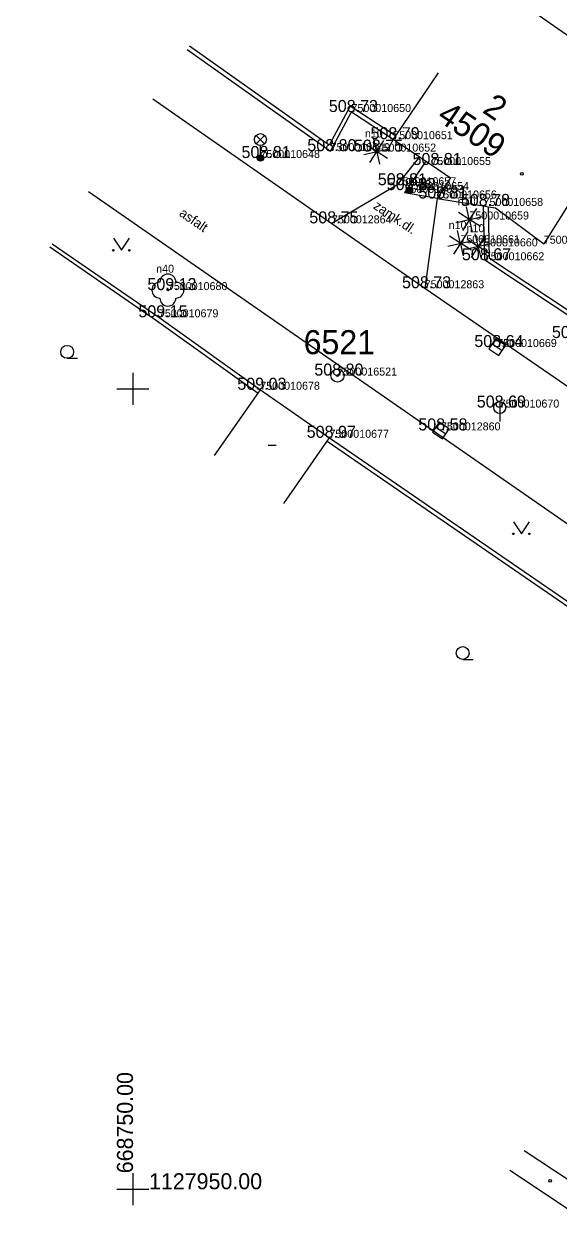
# Model space of a CAD drawing. Extents: x -669251 to -668549, y -1128351 to -1127698.
# Drawn here: x -668756.8 to -668723.4, y -1127952.2 to -1127877.2 of the extents above; entities that cross this region are included whole.
import ezdxf

# ---------------------------------------------------------------- set-up
doc = ezdxf.new("R2010")
doc.units = 0
for name, color, linetype in [('Vrstva 1', 7, 'Continuous'), ('Vrstva 10', 7, 'Continuous'), ('Vrstva 2', 7, 'Continuous'), ('Vrstva 22', 7, 'Continuous'), ('Vrstva 25', 7, 'Continuous'), ('Vrstva 27', 7, 'Continuous'), ('Vrstva 3', 7, 'Continuous'), ('Vrstva 33', 7, 'Continuous'), ('Vrstva 36', 7, 'Continuous'), ('Vrstva 40', 7, 'Continuous'), ('Vrstva 43', 7, 'Continuous'), ('Vrstva 44', 7, 'Continuous'), ('Vrstva 47', 7, 'Continuous'), ('Vrstva 5', 7, 'Continuous'), ('Vrstva 58', 7, 'Continuous'), ('Vrstva 6', 7, 'Continuous'), ('Vrstva 60', 7, 'Continuous'), ('Vrstva 61', 7, 'Continuous'), ('Vrstva 63', 7, 'Continuous'), ('Vrstva 7', 7, 'Continuous')]:
    doc.layers.add(name, color=color, linetype=linetype)

msp = doc.modelspace()

# ---------------------------------------------------------------- linework, layer by layer
at = {"layer": 'Vrstva 1'}
for p, q in [((-668736.353, -1127882.701), (-668736.353, -1127882.701)), ((-668733.748, -1127884.401), (-668733.748, -1127884.401)), ((-668737.661, -1127885.149), (-668737.661, -1127885.149)), ((-668734.787, -1127885.176), (-668734.787, -1127885.176)), ((-668742.042, -1127885.577), (-668742.042, -1127885.577)), ((-668731.363, -1127886.012), (-668731.363, -1127886.012)), ((-668733.532, -1127887.278), (-668733.532, -1127887.278)), ((-668733.047, -1127887.76), (-668733.047, -1127887.76)), ((-668732.736, -1127887.581), (-668732.736, -1127887.581)), ((-668730.996, -1127888.106), (-668730.996, -1127888.106)), ((-668728.108, -1127888.57), (-668728.108, -1127888.57)), ((-668737.572, -1127889.659), (-668737.572, -1127889.659)), ((-668728.99, -1127889.418), (-668728.99, -1127889.418)), ((-668729.552, -1127890.9), (-668729.552, -1127890.9)), ((-668728.441, -1127891.098), (-668728.441, -1127891.098)), ((-668724.345, -1127890.931), (-668724.345, -1127890.931)), ((-668728.03, -1127891.964), (-668728.03, -1127891.964)), ((-668747.821, -1127893.828), (-668747.821, -1127893.828)), ((-668731.783, -1127893.713), (-668731.783, -1127893.713)), ((-668748.384, -1127895.528), (-668748.384, -1127895.528)), ((-668727.254, -1127897.385), (-668727.254, -1127897.385)), ((-668737.225, -1127899.168), (-668737.225, -1127899.168)), ((-668742.046, -1127900.053), (-668742.046, -1127900.053)), ((-668727.097, -1127901.167), (-668727.097, -1127901.167)), ((-668737.732, -1127903.055), (-668737.732, -1127903.055)), ((-668730.766, -1127902.593), (-668730.766, -1127902.593))]:
    msp.add_line(p, q, dxfattribs=at)
at = {"layer": 'Vrstva 10'}
for p, q in [((-668748.761, -1127881.88), (-668737.572, -1127889.659)), ((-668732.109, -1127885.508), (-668733.532, -1127887.278)), ((-668733.532, -1127887.278), (-668737.572, -1127889.659)), ((-668752.783, -1127887.669), (-668717.669, -1127912.036)), ((-668730.996, -1127888.106), (-668731.783, -1127893.713)), ((-668737.572, -1127889.659), (-668731.783, -1127893.713)), ((-668731.783, -1127893.713), (-668696.792, -1127917.771))]:
    msp.add_line(p, q, dxfattribs=at)
at = {"layer": 'Vrstva 22'}
for p, q in [((-668734.795, -1127885.136), (-668734.967, -1127884.382)), ((-668734.353, -1127884.486), (-668734.767, -1127885.142)), ((-668735.581, -1127885.356), (-668734.827, -1127885.184)), ((-668734.821, -1127885.156), (-668735.477, -1127884.742)), ((-668734.807, -1127885.21), (-668735.221, -1127885.866)), ((-668734.779, -1127885.216), (-668734.607, -1127885.97)), ((-668734.097, -1127885.61), (-668734.753, -1127885.196)), ((-668734.747, -1127885.168), (-668733.993, -1127884.996)), ((-668729.024, -1127889.398), (-668729.68, -1127888.984)), ((-668728.998, -1127889.378), (-668729.17, -1127888.624)), ((-668728.556, -1127888.728), (-668728.97, -1127889.384)), ((-668729.784, -1127889.598), (-668729.03, -1127889.426)), ((-668729.01, -1127889.452), (-668729.424, -1127890.108)), ((-668728.982, -1127889.458), (-668728.81, -1127890.212)), ((-668728.3, -1127889.852), (-668728.956, -1127889.438)), ((-668728.95, -1127889.41), (-668728.196, -1127889.238)), ((-668729.586, -1127890.88), (-668730.242, -1127890.466)), ((-668729.56, -1127890.86), (-668729.732, -1127890.106)), ((-668729.118, -1127890.21), (-668729.532, -1127890.866)), ((-668728.449, -1127891.058), (-668728.621, -1127890.304)), ((-668728.007, -1127890.408), (-668728.421, -1127891.064)), ((-668730.346, -1127891.08), (-668729.592, -1127890.908)), ((-668729.572, -1127890.934), (-668729.986, -1127891.59)), ((-668729.544, -1127890.94), (-668729.372, -1127891.694)), ((-668728.862, -1127891.334), (-668729.518, -1127890.92)), ((-668729.512, -1127890.892), (-668728.758, -1127890.72)), ((-668729.235, -1127891.278), (-668728.481, -1127891.106)), ((-668728.475, -1127891.078), (-668729.131, -1127890.664)), ((-668728.461, -1127891.132), (-668728.875, -1127891.788)), ((-668728.433, -1127891.138), (-668728.261, -1127891.892)), ((-668727.751, -1127891.532), (-668728.407, -1127891.118)), ((-668728.401, -1127891.09), (-668727.647, -1127890.918))]:
    msp.add_line(p, q, dxfattribs=at)
for centre, radius in [((-668734.787, -1127885.176), 0.04), ((-668728.99, -1127889.418), 0.04), ((-668729.552, -1127890.9), 0.04), ((-668728.441, -1127891.098), 0.04), ((-668747.821, -1127893.828), 0.05)]:
    msp.add_circle(centre, radius, dxfattribs=at)
for centre, start, end in [((-668748.321, -1127893.828), 90, 270), ((-668747.821, -1127893.328), 0, 180), ((-668747.321, -1127893.828), 270, 90), ((-668747.821, -1127894.328), 180, 0)]:
    msp.add_arc(centre, 0.5, start, end, dxfattribs=at)
at = {"layer": 'Vrstva 25'}
for radius in [0.2, 0.18, 0.16, 0.14, 0.12, 0.1, 0.08, 0.06, 0.04, 0.02]:
    msp.add_circle((-668732.736, -1127887.581), radius, dxfattribs=at)
at = {"layer": 'Vrstva 27'}
for p, q in [((-668727.567, -1127897.178), (-668726.941, -1127897.592)), ((-668727.097, -1127900.792), (-668727.097, -1127902.042)), ((-668731.079, -1127902.386), (-668730.453, -1127902.8))]:
    msp.add_line(p, q, dxfattribs=at)
for points in [[(-668727.773, -1127897.49), (-668727.148, -1127897.904), (-668726.734, -1127897.279), (-668727.359, -1127896.864)], [(-668731.285, -1127902.698), (-668730.66, -1127903.112), (-668730.246, -1127902.487), (-668730.871, -1127902.072)]]:
    msp.add_lwpolyline(points, close=True, dxfattribs=at)
msp.add_circle((-668727.097, -1127901.167), 0.375, dxfattribs=at)
at = {"layer": 'Vrstva 33'}
for p, q in [((-668742.307, -1127884.162), (-668741.777, -1127884.692)), ((-668742.307, -1127884.692), (-668741.777, -1127884.162)), ((-668742.042, -1127885.577), (-668742.042, -1127884.802))]:
    msp.add_line(p, q, dxfattribs=at)
for centre, radius in [((-668742.042, -1127884.427), 0.375), ((-668742.042, -1127885.577), 0.2), ((-668742.042, -1127885.577), 0.18), ((-668742.042, -1127885.577), 0.16), ((-668742.042, -1127885.577), 0.14), ((-668742.042, -1127885.577), 0.12), ((-668742.042, -1127885.577), 0.1), ((-668742.042, -1127885.577), 0.08), ((-668742.042, -1127885.577), 0.06), ((-668742.042, -1127885.577), 0.04), ((-668742.042, -1127885.577), 0.02)]:
    msp.add_circle(centre, radius, dxfattribs=at)
at = {"layer": 'Vrstva 36'}
for p, q in [((-668751.224, -1127890.593), (-668750.724, -1127891.343)), ((-668750.724, -1127891.343), (-668750.224, -1127890.593)), ((-668754.111, -1127898.089), (-668753.461, -1127898.086)), ((-668726.243, -1127908.306), (-668725.743, -1127909.056)), ((-668725.743, -1127909.056), (-668725.243, -1127908.306)), ((-668729.408, -1127916.903), (-668728.758, -1127916.9))]:
    msp.add_line(p, q, dxfattribs=at)
for centre, radius in [((-668751.224, -1127891.343), 0.05), ((-668750.224, -1127891.343), 0.05), ((-668754.111, -1127897.686), 0.403), ((-668726.243, -1127909.056), 0.05), ((-668725.243, -1127909.056), 0.05), ((-668729.408, -1127916.5), 0.403)]:
    msp.add_circle(centre, radius, dxfattribs=at)
at = {"layer": 'Vrstva 5'}
for p, q in [((-668730.949, -1127880.258), (-668733.608, -1127884.194)), ((-668733.608, -1127884.194), (-668733.748, -1127884.401)), ((-668733.748, -1127884.401), (-668732.109, -1127885.508)), ((-668731.709, -1127885.779), (-668733.047, -1127887.76)), ((-668732.109, -1127885.508), (-668731.709, -1127885.779)), ((-668731.709, -1127885.779), (-668731.363, -1127886.012)), ((-668721.688, -1127886.696), (-668724.345, -1127890.931)), ((-668730.161, -1127886.824), (-668730.996, -1127888.106)), ((-668730.996, -1127888.106), (-668733.047, -1127887.76)), ((-668730.996, -1127888.106), (-668728.108, -1127888.57)), ((-668728.108, -1127888.57), (-668727.807, -1127888.618)), ((-668727.807, -1127888.618), (-668727.367, -1127888.689)), ((-668727.367, -1127888.689), (-668724.345, -1127890.931)), ((-668744.902, -1127904.157), (-668742.189, -1127900.258)), ((-668742.189, -1127900.258), (-668742.046, -1127900.053)), ((-668742.046, -1127900.053), (-668737.732, -1127903.055)), ((-668740.588, -1127907.159), (-668737.875, -1127903.26)), ((-668737.875, -1127903.26), (-668737.732, -1127903.055)), ((-668725.569, -1127947.576), (-668721.466, -1127950.301)), ((-668726.472, -1127948.8), (-668722.307, -1127951.567))]:
    msp.add_line(p, q, dxfattribs=at)
at = {"layer": 'Vrstva 58'}
msp.add_line((-668741.549, -1127903.521), (-668741.049, -1127903.521), dxfattribs=at)
for centre, radius in [((-668725.717, -1127886.561), 0.0875), ((-668731.568, -1127887.083), 0.125), ((-668723.946, -1127949.472), 0.0875)]:
    msp.add_circle(centre, radius, dxfattribs=at)
at = {"layer": 'Vrstva 6'}
msp.add_line((-668731.363, -1127886.012), (-668730.161, -1127886.824), dxfattribs=at)
at = {"layer": 'Vrstva 60'}
msp.add_lwpolyline([(-668788.581, -1128325.447), (-668557.456, -1127992.872), (-668787.384, -1127833.082), (-669018.509, -1128165.657)], close=True, dxfattribs=at)
at = {"layer": 'Vrstva 61'}
for p, q in [((-668750, -1127899), (-668750, -1127901)), ((-668751, -1127900), (-668749, -1127900)), ((-668750, -1127949), (-668750, -1127951)), ((-668751, -1127950), (-668749, -1127950))]:
    msp.add_line(p, q, dxfattribs=at)
at = {"layer": 'Vrstva 63'}
for radius in [0.412, 0.412, 0.05, 0.05]:
    msp.add_circle((-668737.225, -1127899.168), radius, dxfattribs=at)
at = {"layer": 'Vrstva 7'}
for p, q in [((-668746.612, -1127878.789), (-668737.661, -1127885.149)), ((-668737.748, -1127884.781), (-668746.469, -1127878.583)), ((-668736.445, -1127882.343), (-668737.748, -1127884.781)), ((-668737.661, -1127885.149), (-668736.353, -1127882.701)), ((-668733.608, -1127884.194), (-668736.445, -1127882.343)), ((-668736.353, -1127882.701), (-668733.748, -1127884.401)), ((-668728.03, -1127891.964), (-668728.108, -1127888.57)), ((-668727.732, -1127891.861), (-668727.807, -1127888.618)), ((-668755.191, -1127891.134), (-668748.528, -1127895.733)), ((-668755.049, -1127890.928), (-668748.384, -1127895.528)), ((-668720.183, -1127897.162), (-668728.03, -1127891.964)), ((-668720.045, -1127896.954), (-668727.732, -1127891.861)), ((-668748.528, -1127895.733), (-668742.189, -1127900.258)), ((-668748.384, -1127895.528), (-668742.046, -1127900.053)), ((-668737.875, -1127903.26), (-668719.894, -1127915.619)), ((-668737.732, -1127903.055), (-668719.752, -1127915.413))]:
    msp.add_line(p, q, dxfattribs=at)

# ---------------------------------------------------------------- texts
at = {"layer": 'Vrstva 2'}
for s, p in [('7500010650', (-668736.353, -1127882.701)), ('7500010651', (-668733.748, -1127884.401)), ('7500010648', (-668742.042, -1127885.577)), ('7500010649', (-668737.661, -1127885.149)), ('7500010652', (-668734.787, -1127885.176)), ('7500010655', (-668731.363, -1127886.012)), ('7500010657', (-668733.532, -1127887.278)), ('7500010653', (-668733.047, -1127887.76)), ('7500010654', (-668732.736, -1127887.581)), ('7500010656', (-668730.996, -1127888.106)), ('7500010658', (-668728.108, -1127888.57)), ('7500010659', (-668728.99, -1127889.418)), ('7500012864', (-668737.572, -1127889.659)), ('7500010661', (-668729.552, -1127890.9)), ('7500010663', (-668724.345, -1127890.931)), ('7500010660', (-668728.441, -1127891.098)), ('7500010662', (-668728.03, -1127891.964)), ('7500010680', (-668747.821, -1127893.828)), ('7500012863', (-668731.783, -1127893.713)), ('7500010679', (-668748.384, -1127895.528)), ('7500010669', (-668727.254, -1127897.385)), ('7500016521', (-668737.225, -1127899.168)), ('7500010678', (-668742.046, -1127900.053)), ('7500010670', (-668727.097, -1127901.167)), ('7500012860', (-668730.766, -1127902.593)), ('7500010677', (-668737.732, -1127903.055))]:
    msp.add_text(s, height=0.5, dxfattribs=at).set_placement(p)
at = {"layer": 'Vrstva 3'}
for s, p in [('508.73 ', (-668737.768, -1127882.701)), ('508.79 ', (-668735.166, -1127884.401)), ('508.80 ', (-668739.112, -1127885.149)), ('508.75 ', (-668736.202, -1127885.176)), ('508.81 ', (-668743.22, -1127885.577)), ('508.81 ', (-668732.541, -1127886.012)), ('508.81 ', (-668734.71, -1127887.278)), ('508.82 ', (-668734.151, -1127887.581)), ('508.81 ', (-668732.174, -1127888.106)), ('508.78 ', (-668729.523, -1127888.57)), ('508.75 ', (-668738.987, -1127889.659)), ('508.67 ', (-668729.459, -1127891.964)), ('509.13 ', (-668749.097, -1127893.828)), ('508.73 ', (-668733.198, -1127893.713)), ('509.15 ', (-668749.66, -1127895.528)), ('508.64 ', (-668723.837, -1127896.822)), ('508.64 ', (-668728.683, -1127897.385)), ('508.80 ', (-668738.676, -1127899.168)), ('509.03 ', (-668743.484, -1127900.053)), ('508.69 ', (-668728.529, -1127901.167)), ('508.97 ', (-668739.149, -1127903.055)), ('508.58 ', (-668732.181, -1127902.593))]:
    msp.add_text(s, height=0.75, dxfattribs=at).set_placement(p)
at = {"layer": 'Vrstva 40'}
for s, rotation, p in [('asfalt', 325.39672, (-668747.166, -1127889.149)), ('zamk.dl.', 325.96209, (-668735.042, -1127888.695))]:
    msp.add_text(s, height=0.6, rotation=rotation, dxfattribs=at).set_placement(p)
at = {"layer": 'Vrstva 43'}
msp.add_text('4509', height=1.5, rotation=325.96209, dxfattribs=at).set_placement((-668731.093, -1127883.178))
at = {"layer": 'Vrstva 44'}
msp.add_text('2', height=1.5, rotation=325.96209, dxfattribs=at).set_placement((-668728.24, -1127882.691))
at = {"layer": 'Vrstva 47'}
for s, height, p in [('n10', 0.5, (-668735.517, -1127884.29)), ('n10', 0.5, (-668729.72, -1127888.532)), ('n10', 0.5, (-668730.282, -1127890.014)), ('n10', 0.5, (-668729.171, -1127890.212)), ('n40', 0.499, (-668748.55, -1127892.742))]:
    msp.add_text(s, height=height, dxfattribs=at).set_placement(p)
at = {"layer": 'Vrstva 61'}
msp.add_text('668750.00', height=1, rotation=90, dxfattribs=at).set_placement((-668750, -1127949))
msp.add_text('1127950.00', height=1, dxfattribs=at).set_placement((-668749, -1127950))
at = {"layer": 'Vrstva 63'}
msp.add_text('6521', height=1.5, dxfattribs=at).set_placement((-668739.344, -1127897.831))
msp.add_text('6521', height=1.5, dxfattribs=at).set_placement((-668739.344, -1127897.831))

doc.saveas('drawing.dxf')
